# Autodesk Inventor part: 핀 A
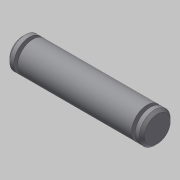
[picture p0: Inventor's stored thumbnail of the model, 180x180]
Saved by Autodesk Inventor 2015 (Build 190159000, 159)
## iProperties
Created: 2020-02
Part Number: 핀 A
Material: 스테인리스강
Document SubType Name: Modeling
Designer: mduedu
Density: 1 g/cm^3
Appearance: 기본값
Author: mduedu
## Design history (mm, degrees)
sketch "스케치1"
  geometry: L1 (0, 0)-(26, 0); L2 (26, 0)-(26, 3); L3 (26, 3)-(0, 3); L4 (0, 3)-(0, 0)
  constraints: 8 end point, 2 parallel, 1 horizontal, 1 perpendicular
  dimensions: "d0" = 26 distance of L2.end L3.end; "d2" = 6 diameter of L3 L1
revolve "회전1" sketch "스케치1" stored, may be unused: angle "d3" = 90 deg
sketch "스케치2"
  geometry: L1 (0, -3)-(0, 3) reference; L2 (0, 3)-(26, 3) reference; L3 (26, 3)-(26, -3) reference; L4 (26, -3)-(0, -3) reference; L5 (0, 0)-(26, 0); L6 (1.3, 3)-(2, 3); L7 (2, 3)-(2, 2); L8 (2, 2)-(1.3, 2); L9 (1.3, 2)-(1.3, 3)
  constraints: 10 end point, 2 parallel, 1 horizontal, 1 midpoint, 1 perpendicular, 1 point on line
  dimensions: "d4" = 4 diameter of L8 L5; "d6" = 1.3 distance between parallel lines of L9 L1; "d7" = 0.7 distance between parallel lines of L7 L9
revolve "회전2" sketch "스케치2" stored, may be unused: angle "d8" = 90 deg
node "작업 평면1"
chamfer "모따기1" distance "d9" = 0.5; stored, may be unused: second distance "d10" = 2, angle "d11" = 45 deg
node "솔리드1"
mirror "대칭1"
node "절단 모서리 투영1"
